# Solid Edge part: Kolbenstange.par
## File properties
Last saved by: ahadarics
Revision: 76
Dokumentum tartalom típus: 0
Sűrűség: 0,000 kg/m^3
Pontosság: 0,990
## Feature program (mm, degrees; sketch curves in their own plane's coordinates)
base feature "unnamed BaseFeature 1"
thread "unnamed Thread 1"
sketch for "unnamed Protrusion 1" plane through (0, 0, -37.5) normal (0, 0, -1) x-axis (0, -1, 0)
  circle centre (0, 0) radius 20
extrude "unnamed Protrusion 1" add finite 16 along -normal
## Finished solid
Body 1: solid body, 17 faces, 23 edges, 8 vertices.
  Faces by surface: plane 8, cylinder 4, torus 3, cone 2
  Edges by curve: circle 13, line 6, ellipse 2, intersection 2
Bounding box of the edges (mm; curved faces can reach further): 40.000 x 40.000 x 61.500, from (-20, -20, -37.5) to (20, 20, 24).
Cylindrical faces by radius (mm): R3.95 x1, R5 x1, R6 x1, R20 x1
Conical faces (half-angle, radius in mm at the cone's reference point): 20 deg R4.5 x1, 60 deg R4.575 x1
Toroidal faces (ring radius, tube radius in mm): R4.35 r0.4 x2, R4.8 r1.2 x1
Planar faces by outward normal: +x 1, +z 3, -x 1, -z 1, oblique 2
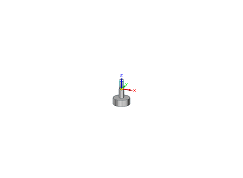
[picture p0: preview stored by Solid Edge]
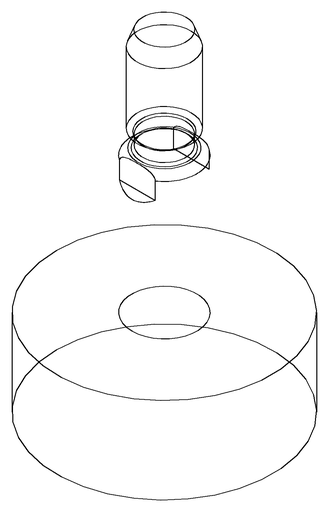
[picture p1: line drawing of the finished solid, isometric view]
